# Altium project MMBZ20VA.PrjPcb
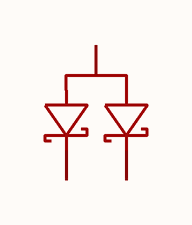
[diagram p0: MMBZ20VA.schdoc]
1 sheet, 1 parts. Net scope: global (net labels, ports and power ports of the same name join across sheets).

## Sheet MMBZ20VA.schdoc
size 127 x 101 mm

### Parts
U?  mmbz20va  [SOT-23-3_L2.9-W1.3-P1.90-LS2.4-BR]  (value not drawn)

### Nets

Not connected (* = marked no-connect by the designer): U? 1 2 3

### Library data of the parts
U? = mmbz20va: 极性:单向;反向截止电压(Vrwm):17V;钳位电压:28V;峰值脉冲电流(Ipp):1.4A;峰值脉冲功率(Ppp):40W;击穿电压(VBR):19V;; Manufacturer: JSMSEMI(杰盛微); AddInBom: yes; ModelId: c62791f0466c4ae2a892c056b845b0ca; ModelName: SOT-23-3P_L2.9-W1.3-H1.0-LS2.4-P0.95; ModelTransform: 98.425,114.173,0,180,0,0,0.0005,-0.0005,0; Polarity: 单向; Reverse Stand-Off Voltage (Vrwm): 17V; Clamping Voltage: 28V; Peak Pulse Current (Ipp): 1.4A; Peak Pulse Power Dissipation (Ppp): 40W; Voltage - Breakdown: 19V; Reverse Leakage Current (Ir): 50nA; Number of Channels: 双路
